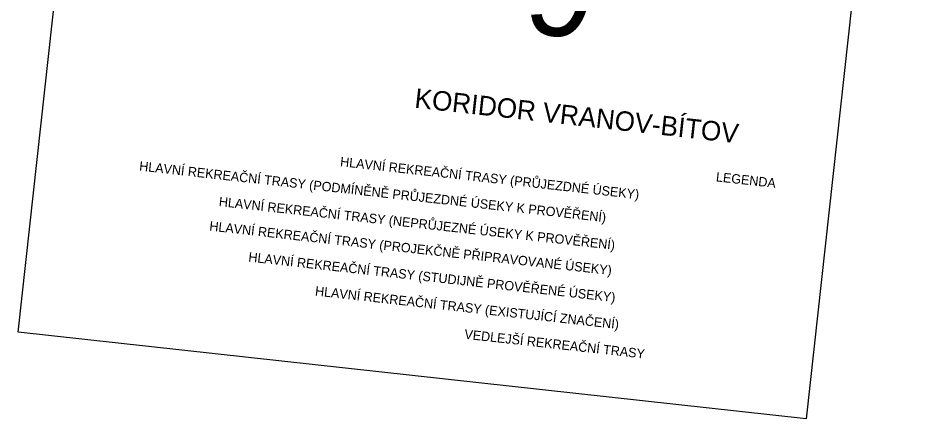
# Model space of a CAD drawing. Extents: x -678204 to -526855, y -1228851 to -1110393.
# Drawn here: x -675119 to -651868, y -1204345 to -1194100 of the extents above; entities that cross this region are included whole.
import ezdxf

# ---------------------------------------------------------------- set-up
doc = ezdxf.new("R2010")
doc.units = 0
for name, color, linetype in [('00_n_legenda popisy', 7, 'Continuous'), ('00_n_legenda popisy_hlavni', 7, 'Continuous'), ('_HELP BIG', 7, 'Continuous')]:
    doc.layers.add(name, color=color, linetype=linetype)

msp = doc.modelspace()

# ---------------------------------------------------------------- linework, layer by layer
at = {"layer": '_HELP BIG'}
msp.add_lwpolyline([(-675119, -1202133), (-672013, -1173846), (-651868, -1176058), (-654974, -1204345)], close=True, dxfattribs=at)

# ---------------------------------------------------------------- texts
at = {"layer": '00_n_legenda popisy'}
for s, p in [('HLAVNÍ REKREAČNÍ TRASY (PRŮJEZDNÉ ÚSEKY) ', (-666899, -1197883)), ('HLAVNÍ REKREAČNÍ TRASY (PODMÍNĚNĚ PRŮJEZDNÉ ÚSEKY K PROVĚŘENÍ) ', (-672034, -1197996)), ('LEGENDA', (-657292, -1198271)), ('HLAVNÍ REKREAČNÍ TRASY (NEPRŮJEZNÉ ÚSEKY K PROVĚŘENÍ) ', (-669999, -1198903)), ('HLAVNÍ REKREAČNÍ TRASY (PROJEKČNĚ PŘIPRAVOVANÉ ÚSEKY) ', (-670241, -1199531)), ('HLAVNÍ REKREAČNÍ TRASY (STUDIJNĚ PROVĚŘENÉ ÚSEKY) ', (-669244, -1200322)), ('HLAVNÍ REKREAČNÍ TRASY (EXISTUJÍCÍ ZNAČENÍ) ', (-667540, -1201192)), ('VEDLEJŠÍ REKREAČNÍ TRASY ', (-663723, -1202296))]:
    msp.add_text(s, height=240, rotation=353.6836, dxfattribs=at).set_placement(p)
at = {"layer": '00_n_legenda popisy_hlavni'}
msp.add_text('KORIDOR VRANOV-BÍTOV', height=497.66, rotation=353.6836, dxfattribs=at).set_placement((-665004, -1196385))
at = {"layer": '_HELP BIG'}
msp.add_text('9', height=2400, rotation=353.6836, dxfattribs=at).set_placement((-662254, -1194453))

doc.saveas('drawing.dxf')
